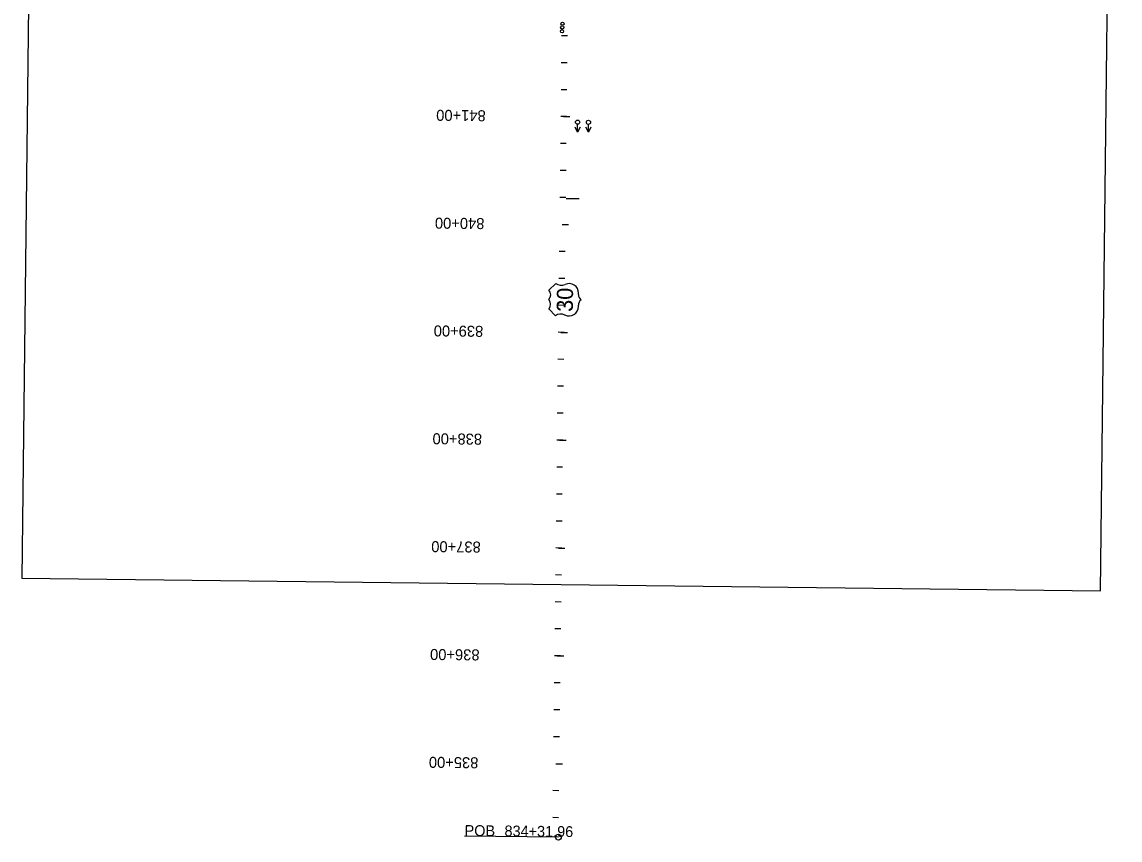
# Model space of a CAD drawing. Extents: x 16507806 to 16508824, y 7132703 to 7134669.
# Drawn here: x 16507806 to 16508824, y 7132703 to 7133461 of the extents above; entities that cross this region are included whole.
import ezdxf

# ---------------------------------------------------------------- set-up
doc = ezdxf.new("R2010")
doc.units = 0
for name, color, linetype in [('dsnCellsHighwaySymbols', 7, 'Continuous'), ('Level 2', 7, 'Continuous'), ('NamedBoundary', 7, 'Continuous'), ('PavementMarking', 7, 'Continuous'), ('phoCulvert', 7, 'Continuous'), ('TextAlignment', 7, 'Continuous'), ('TextAlignmentLrg', 7, 'Continuous'), ('TextAlignmentSml', 7, 'Continuous')]:
    doc.layers.add(name, color=color, linetype=linetype)

msp = doc.modelspace()

# ---------------------------------------------------------------- linework, layer by layer
at = {"layer": 'dsnCellsHighwaySymbols'}
for p, q in [((16508300.7, 7133218.9), (16508294.4, 7133212.7)), ((16508300.7, 7133218.9), (16508294.4, 7133212.7)), ((16508321.8, 7133208.7), (16508321.8, 7133209.9)), ((16508321.8, 7133208.7), (16508321.8, 7133209.9)), ((16508294.2, 7133195.2), (16508300.4, 7133188.9)), ((16508294.2, 7133195.2), (16508300.4, 7133188.9)), ((16508321.7, 7133197.4), (16508321.7, 7133198.7)), ((16508321.7, 7133197.4), (16508321.7, 7133198.7))]:
    msp.add_line(p, q, dxfattribs=at)
for centre, radius, start, end in [((16508289.9, 7133208.4), 6.25, 314.9199, 43.7742), ((16508289.9, 7133208.4), 6.25, 314.9199, 43.7742), ((16508305.9, 7133226), 8.75, 233.6843, 294.3571), ((16508305.9, 7133226), 8.75, 233.6843, 294.3571), ((16508313.1, 7133210), 8.75, 359.3471, 114.3575), ((16508313.1, 7133210), 8.75, 359.3471, 114.3575), ((16508289.8, 7133199.6), 6.25, 314.9199, 43.7742), ((16508289.8, 7133199.6), 6.25, 314.9199, 43.7742), ((16508328, 7133198.6), 6.25, 126.2169, 179.3472), ((16508328, 7133198.6), 6.25, 126.2169, 179.3472), ((16508328.1, 7133208.6), 6.25, 179.3472, 232.477), ((16508328.1, 7133208.6), 6.25, 179.3472, 232.477), ((16508313, 7133197.5), 8.75, 244.3367, 359.3471), ((16508313, 7133197.5), 8.75, 244.3367, 359.3471), ((16508305.4, 7133181.7), 8.75, 64.3365, 125.0099), ((16508305.4, 7133181.7), 8.75, 64.3365, 125.0099)]:
    msp.add_arc(centre, radius, start, end, dxfattribs=at)
at = {"layer": 'Level 2'}
for p, q in [((16508320.9, 7133359.2), (16508318.7, 7133363.8)), ((16508320.9, 7133359.2), (16508321, 7133366.5)), ((16508323.3, 7133363.8), (16508320.9, 7133359.2)), ((16508331, 7133359.1), (16508328.8, 7133363.7)), ((16508331, 7133359.1), (16508331.1, 7133366.4)), ((16508333.4, 7133363.7), (16508331, 7133359.1))]:
    msp.add_line(p, q, dxfattribs=at)
for centre in [(16508321, 7133368.4), (16508331.1, 7133368.3)]:
    msp.add_circle(centre, 1.94, dxfattribs=at)
at = {"layer": 'NamedBoundary'}
msp.add_lwpolyline([(16507805.9, 7132945.5), (16508805.8, 7132934), (16508823.9, 7134501.4), (16507824, 7134512.9)], close=True, dxfattribs=at)
at = {"layer": 'PavementMarking'}
msp.add_line((16508310.4, 7133297.7), (16508322.4, 7133297.6), dxfattribs=at)
at = {"layer": 'phoCulvert'}
for centre in [(16508306.8, 7133456.2), (16508307, 7133459.7), (16508306.6, 7133452.7)]:
    msp.add_circle(centre, 1.5, dxfattribs=at)
at = {"layer": 'TextAlignment'}
msp.add_line((16508303.2, 7132705.5), (16508216.2, 7132706.5), dxfattribs=at)
msp.add_circle((16508303.2, 7132705.5), 2.67, dxfattribs=at)
at = {"layer": 'TextAlignmentLrg'}
for p, q in [((16508310.8, 7133373.5), (16508305.4, 7133373.5)), ((16508306.6, 7133273.5), (16508312.7, 7133273.5)), ((16508308.5, 7133173.5), (16508303.1, 7133173.6)), ((16508307.4, 7133073.5), (16508301.9, 7133073.6)), ((16508306.3, 7132973.5), (16508300.8, 7132973.6)), ((16508305.1, 7132873.5), (16508299.7, 7132873.6)), ((16508300.9, 7132773.6), (16508307, 7132773.5))]:
    msp.add_line(p, q, dxfattribs=at)
at = {"layer": 'TextAlignmentSml'}
for p, q in [((16508311.7, 7133448.5), (16508306.2, 7133448.5)), ((16508311.4, 7133423.5), (16508305.9, 7133423.5)), ((16508311.1, 7133398.5), (16508305.7, 7133398.5)), ((16508307.8, 7133373.5), (16508313.9, 7133373.5)), ((16508310.5, 7133348.5), (16508305.1, 7133348.6)), ((16508310.3, 7133323.5), (16508304.8, 7133323.6)), ((16508310, 7133298.5), (16508304.5, 7133298.6)), ((16508306.6, 7133273.5), (16508312.7, 7133273.5)), ((16508309.4, 7133248.5), (16508303.9, 7133248.6)), ((16508309.1, 7133223.5), (16508303.7, 7133223.6)), ((16508308.8, 7133198.5), (16508303.4, 7133198.6)), ((16508305.5, 7133173.5), (16508311.6, 7133173.5)), ((16508308.3, 7133148.5), (16508302.8, 7133148.6)), ((16508308, 7133123.5), (16508302.5, 7133123.6)), ((16508307.7, 7133098.5), (16508302.2, 7133098.6)), ((16508304.3, 7133073.5), (16508310.5, 7133073.5)), ((16508307.1, 7133048.5), (16508301.7, 7133048.6)), ((16508306.8, 7133023.5), (16508301.4, 7133023.6)), ((16508306.6, 7132998.5), (16508301.1, 7132998.6)), ((16508303.2, 7132973.5), (16508309.3, 7132973.5)), ((16508306, 7132948.5), (16508300.5, 7132948.6)), ((16508305.7, 7132923.5), (16508300.2, 7132923.6)), ((16508305.4, 7132898.5), (16508300, 7132898.6)), ((16508302.1, 7132873.6), (16508308.2, 7132873.5)), ((16508304.8, 7132848.5), (16508299.4, 7132848.6)), ((16508304.6, 7132823.5), (16508299.1, 7132823.6)), ((16508304.3, 7132798.5), (16508298.8, 7132798.6)), ((16508300.9, 7132773.6), (16508307, 7132773.5)), ((16508303.7, 7132748.5), (16508298.2, 7132748.6)), ((16508303.4, 7132723.5), (16508298, 7132723.6))]:
    msp.add_line(p, q, dxfattribs=at)

# ---------------------------------------------------------------- texts
at = {"layer": 'dsnCellsHighwaySymbols'}
msp.add_text('30', height=15, rotation=89.347, dxfattribs=at).set_placement((16508316.6, 7133192.5))
at = {"layer": 'TextAlignment'}
for s, p in [('POB ', (16508216.2, 7132706.7)), ('834+31.96', (16508253.2, 7132706.3))]:
    msp.add_text(s, height=10.02, rotation=359.347, dxfattribs=at).set_placement(p)
at = {"layer": 'TextAlignmentLrg'}
for s, p in [('840+00', (16508234.7, 7133279.4)), ('835+00', (16508229.1, 7132779.5))]:
    msp.add_text(s, height=10.2, rotation=179.347, dxfattribs=at).set_placement(p)
at = {"layer": 'TextAlignmentSml'}
for s, p in [('841+00', (16508235.9, 7133379.4)), ('840+00', (16508234.7, 7133279.4)), ('839+00', (16508233.6, 7133179.5)), ('838+00', (16508232.5, 7133079.5)), ('837+00', (16508231.3, 7132979.5)), ('836+00', (16508230.2, 7132879.5)), ('835+00', (16508229.1, 7132779.5))]:
    msp.add_text(s, height=10.2, rotation=179.347, dxfattribs=at).set_placement(p)

doc.saveas('drawing.dxf')
